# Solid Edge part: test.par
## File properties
Title: Thrust bearing
Author: vicky raina
Template: Normal.par
Last saved by: Robert a Rhodes jr
Revision: 8
Application: Solid Edge
Material: aluminum
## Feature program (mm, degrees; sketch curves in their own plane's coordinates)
sketch for "unnamed RevolvedProtrusion 1" plane through (0, 0, 0) normal (0, -1, 0) x-axis (1, 0, 0)
  line (47.625, 16.8036) -> (66.929, 16.8036)
  line (66.929, 16.8036) -> (73.025, 10.7076)
  line (73.025, 10.7076) -> (73.025, -12.0254)
  line (73.025, -12.0254) -> (66.929, -18.1214)
  line (66.929, -18.1214) -> (47.625, -18.1214)
  line (47.625, -18.1214) -> (47.625, -7.1994)
  line (61.5714, -7.1994) -> (47.625, -7.1994)
  line (61.5714, 5.8816) -> (61.5714, -7.1994)
  line (47.625, 5.8816) -> (61.5714, 5.8816)
  line (47.625, 5.8816) -> (47.625, 16.8036)
revolve "unnamed RevolvedProtrusion 1" add finite 360 deg
sketch for "unnamed RevolvedProtrusion 2" plane through (0, 0, 0) normal (1, 0, 0) x-axis (0, 1, 0)
  line (69.977, 13.7556) -> (73.0652, 13.7556)
  line (73.0652, 13.7556) -> (74.6125, 12.2083)
  line (74.6125, 12.2083) -> (74.6125, -13.4669)
  line (74.6125, -13.4669) -> (73.006, -15.0734)
  line (73.006, -15.0734) -> (69.977, -15.0734)
revolve "unnamed RevolvedProtrusion 2" add full turn 360 deg
sketch for "unnamed RevolvedProtrusion 3" plane through (0, 0, 0) normal (0, -1, 0) x-axis (1, 0, 0)
revolve "unnamed RevolvedProtrusion 3" add full turn 360 deg about sketch line (-54.9674, 10.1232) -> (-54.9674, -18.1214)
pattern "unnamed Pattern 1" of "unnamed RevolvedProtrusion 3"
pattern "unnamed Pattern 2"
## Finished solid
Body 1: solid body, 39 faces, 39 edges, 25 vertices.
  Faces by surface: torus 25, plane 6, cone 4, cylinder 4
  Edges by curve: circle 39
Bounding box of the edges (mm; curved faces can reach further): 149.225 x 149.225 x 34.925, from (-74.6125, -74.6125, -18.1214) to (74.6125, 74.6125, 16.8036).
Cylindrical faces by radius (mm): R47.625 x2, R61.5714 x1, R74.6125 x1
Conical faces (half-angle, radius in mm at the cone's reference point): 45 deg R66.929 x1, 45 deg R73.025 x1, 45 deg R73.0652 x1, 45 deg R74.6125 x1
Toroidal faces (ring radius, tube radius in mm): R-0.1023 r6.604 x25
Planar faces by outward normal: +z 3, -z 3
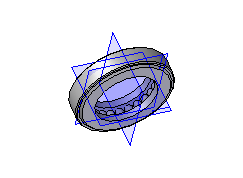
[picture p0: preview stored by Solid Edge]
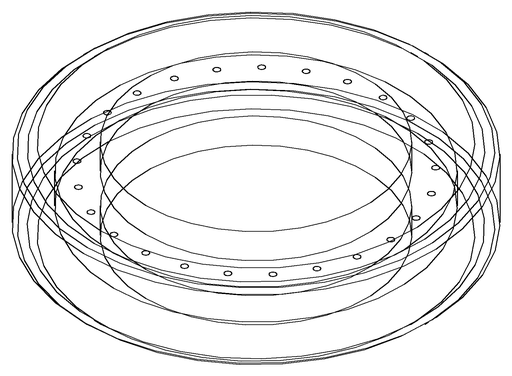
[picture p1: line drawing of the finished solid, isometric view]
